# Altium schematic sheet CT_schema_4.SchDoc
size 288 x 169 mm
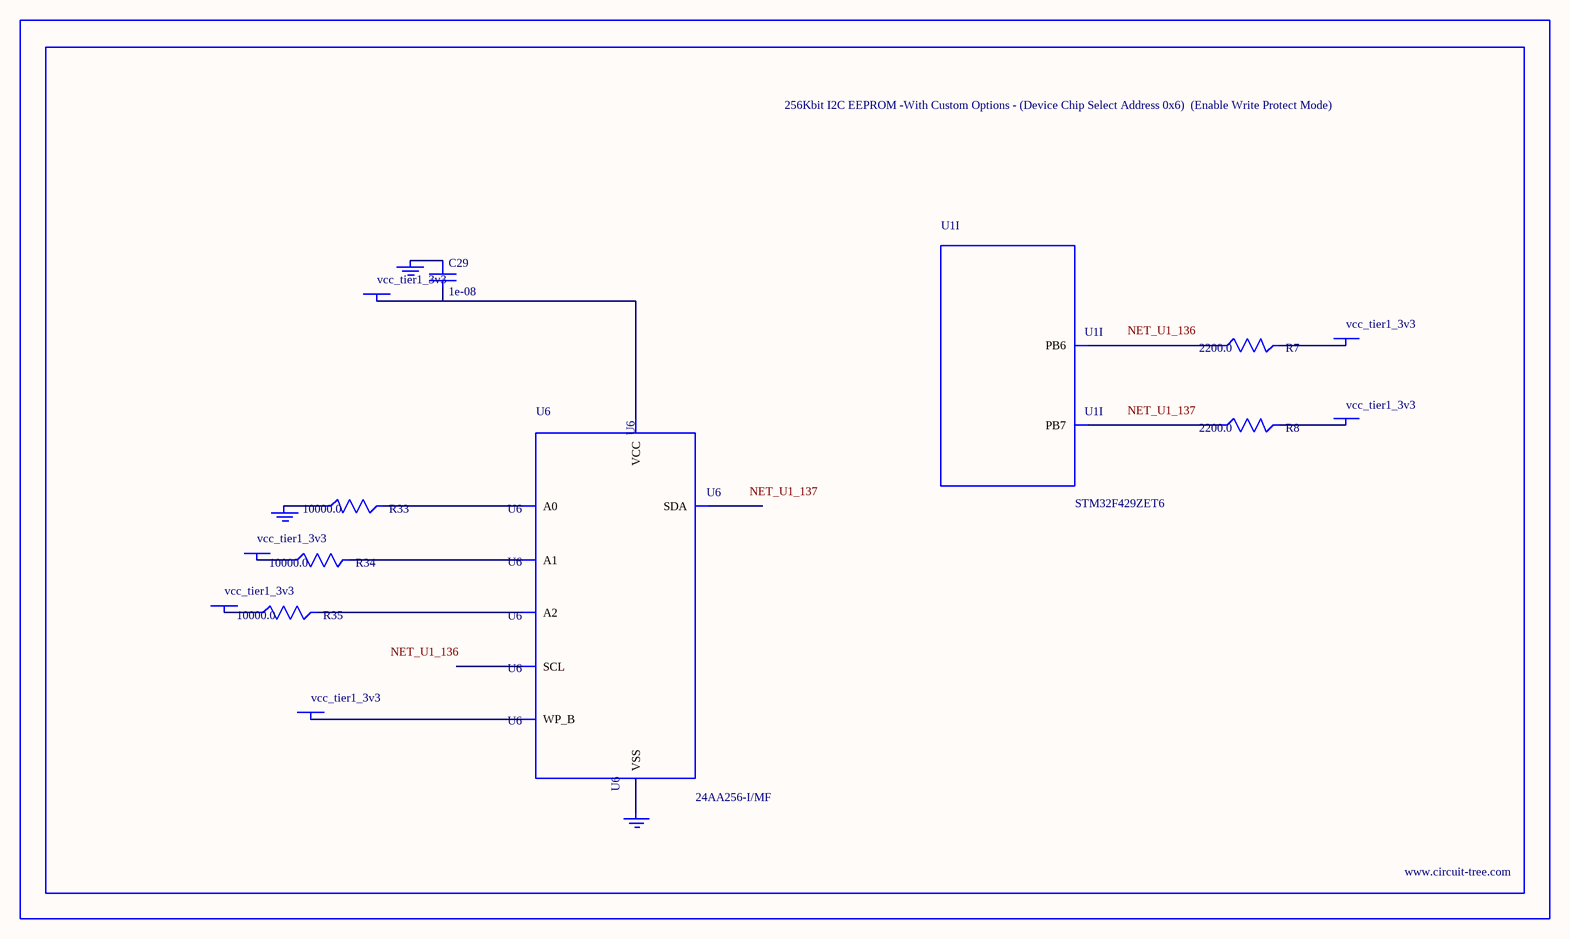
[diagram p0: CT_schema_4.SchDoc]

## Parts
BORDER3  (no value)
C29  1e-08  [C0402]
GND_INSTANCE_3_0  (no value)
GND_INSTANCE_3_1  (no value)
GND_INSTANCE_3_2  (no value)
POWER_INSTANCE_3_0  vcc_tier1_3v3
POWER_INSTANCE_3_1  vcc_tier1_3v3
POWER_INSTANCE_3_2  vcc_tier1_3v3
POWER_INSTANCE_3_3  vcc_tier1_3v3
POWER_INSTANCE_3_4  vcc_tier1_3v3
POWER_INSTANCE_3_5  vcc_tier1_3v3
R7  2200.0  [R0603]
R8  2200.0  [R0603]
R33  10000.0  [R0603]
R34  10000.0  [R0603]
R35  10000.0  [R0603]
U1  STM32F429ZET6  [LQFP144]  (part I of 11)
U6  24AA256-I/MF  [DFN8-S]

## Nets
NetC29_1: C29.1 GND_INSTANCE_3_1.0(GND)
NetC29_2: C29.2 POWER_INSTANCE_3_3.0(PWR) U6.8(VCC)
NetGND_INSTANCE_3_0_0: GND_INSTANCE_3_0.0(GND) R33.1
NetGND_INSTANCE_3_2_0: GND_INSTANCE_3_2.0(GND) U6.4(VSS)
NetPOWER_INSTANCE_3_0_0: POWER_INSTANCE_3_0.0(PWR) R34.1
NetPOWER_INSTANCE_3_1_0: POWER_INSTANCE_3_1.0(PWR) R35.1
NetPOWER_INSTANCE_3_2_0: POWER_INSTANCE_3_2.0(PWR) U6.7(WP_B)
NetPOWER_INSTANCE_3_4_0: POWER_INSTANCE_3_4.0(PWR) R7.2
NetPOWER_INSTANCE_3_5_0: POWER_INSTANCE_3_5.0(PWR) R8.2
NetR7_1: R7.1 U1.136(PB6)
NetR8_1: R8.1 U1.137(PB7)
NetR33_2: R33.2 U6.1(A0)
NetR34_2: R34.2 U6.2(A1)
NetR35_2: R35.2 U6.3(A2)

Not connected (* = marked no-connect by the designer): U6 5(SDA) 6(SCL)

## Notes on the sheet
- Labels drawn without touching a wire or pin: NET_U1_136, NET_U1_137

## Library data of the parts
BORDER3 = BORDER_PAGE3
C29 = C0402C103K3RAC
GND_INSTANCE_3_0-GND_INSTANCE_3_2 = GND
POWER_INSTANCE_3_0-POWER_INSTANCE_3_5 = PWR
R7 R8 = RC0603JR-072K2L
R33-R35 = RC0603JR-0710KL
